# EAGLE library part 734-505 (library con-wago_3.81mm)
Serie 734, Federleiste mit geraden Einlötstiften / Series 734, Female connector with straight solder pins Polzahl / Pole No.: 5 Bemessungsspannung / Rated Voltage: 160 V Nennstrom / Nominal Current: 10 A Lötstiftlänge: / Solder Pin Length: 3.8 mm Farbe / Color: orange / orange Stand: 01.01.2012. Die jeweils aktuellen Daten zu diesem Artikel finden Sie in unserem Produktkatalog, den Sie unter www.wago.com einsehen können. As of: 01/01/2012. Please find the newest data for this article in our product catalogue, which can be viewed under www.wago.com.
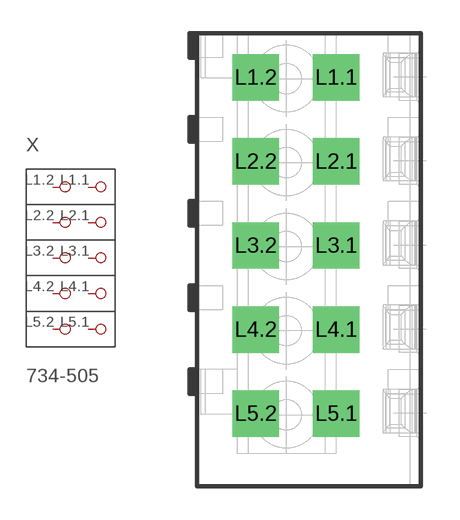
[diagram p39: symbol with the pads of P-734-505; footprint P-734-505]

Designator prefix X

## 734-505  [P-734-505]
L1.1  P1.1
L1.2  P1.2
L2.1  P2.1
L2.2  P2.2
L3.1  P3.1
L3.2  P3.2
L4.1  P4.1
L4.2  P4.2
L5.1  P5.1
L5.2  P5.2

## Footprint P-734-505 (pad centres in mm)
drill 1.4 square: L1.1 1.277,8.265; L1.2 -2.373,8.265; L2.1 1.277,4.455; L2.2 -2.373,4.455; L3.1 1.277,0.645; L3.2 -2.373,0.645; L4.1 1.277,-3.165; L4.2 -2.373,-3.165; L5.1 1.277,-6.975; L5.2 -2.373,-6.975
